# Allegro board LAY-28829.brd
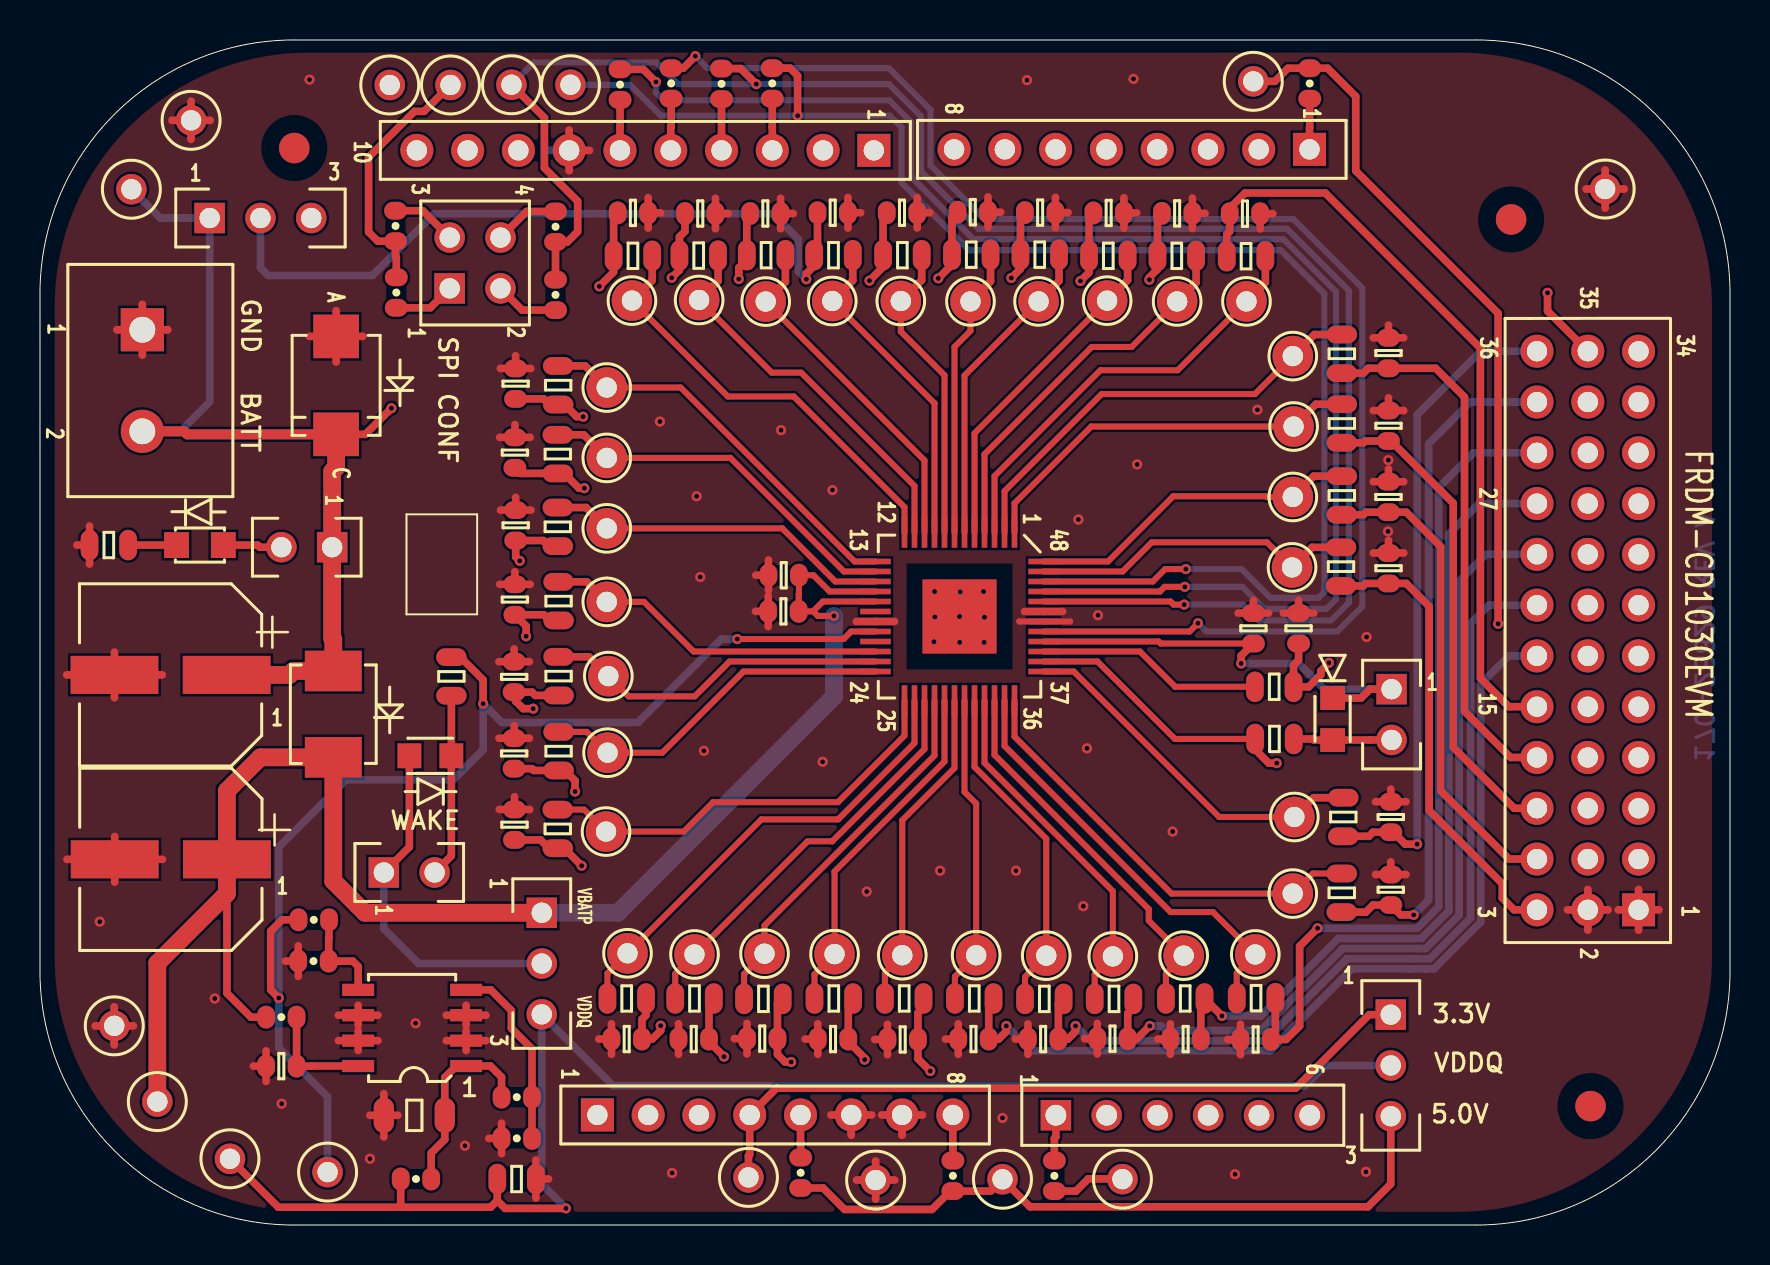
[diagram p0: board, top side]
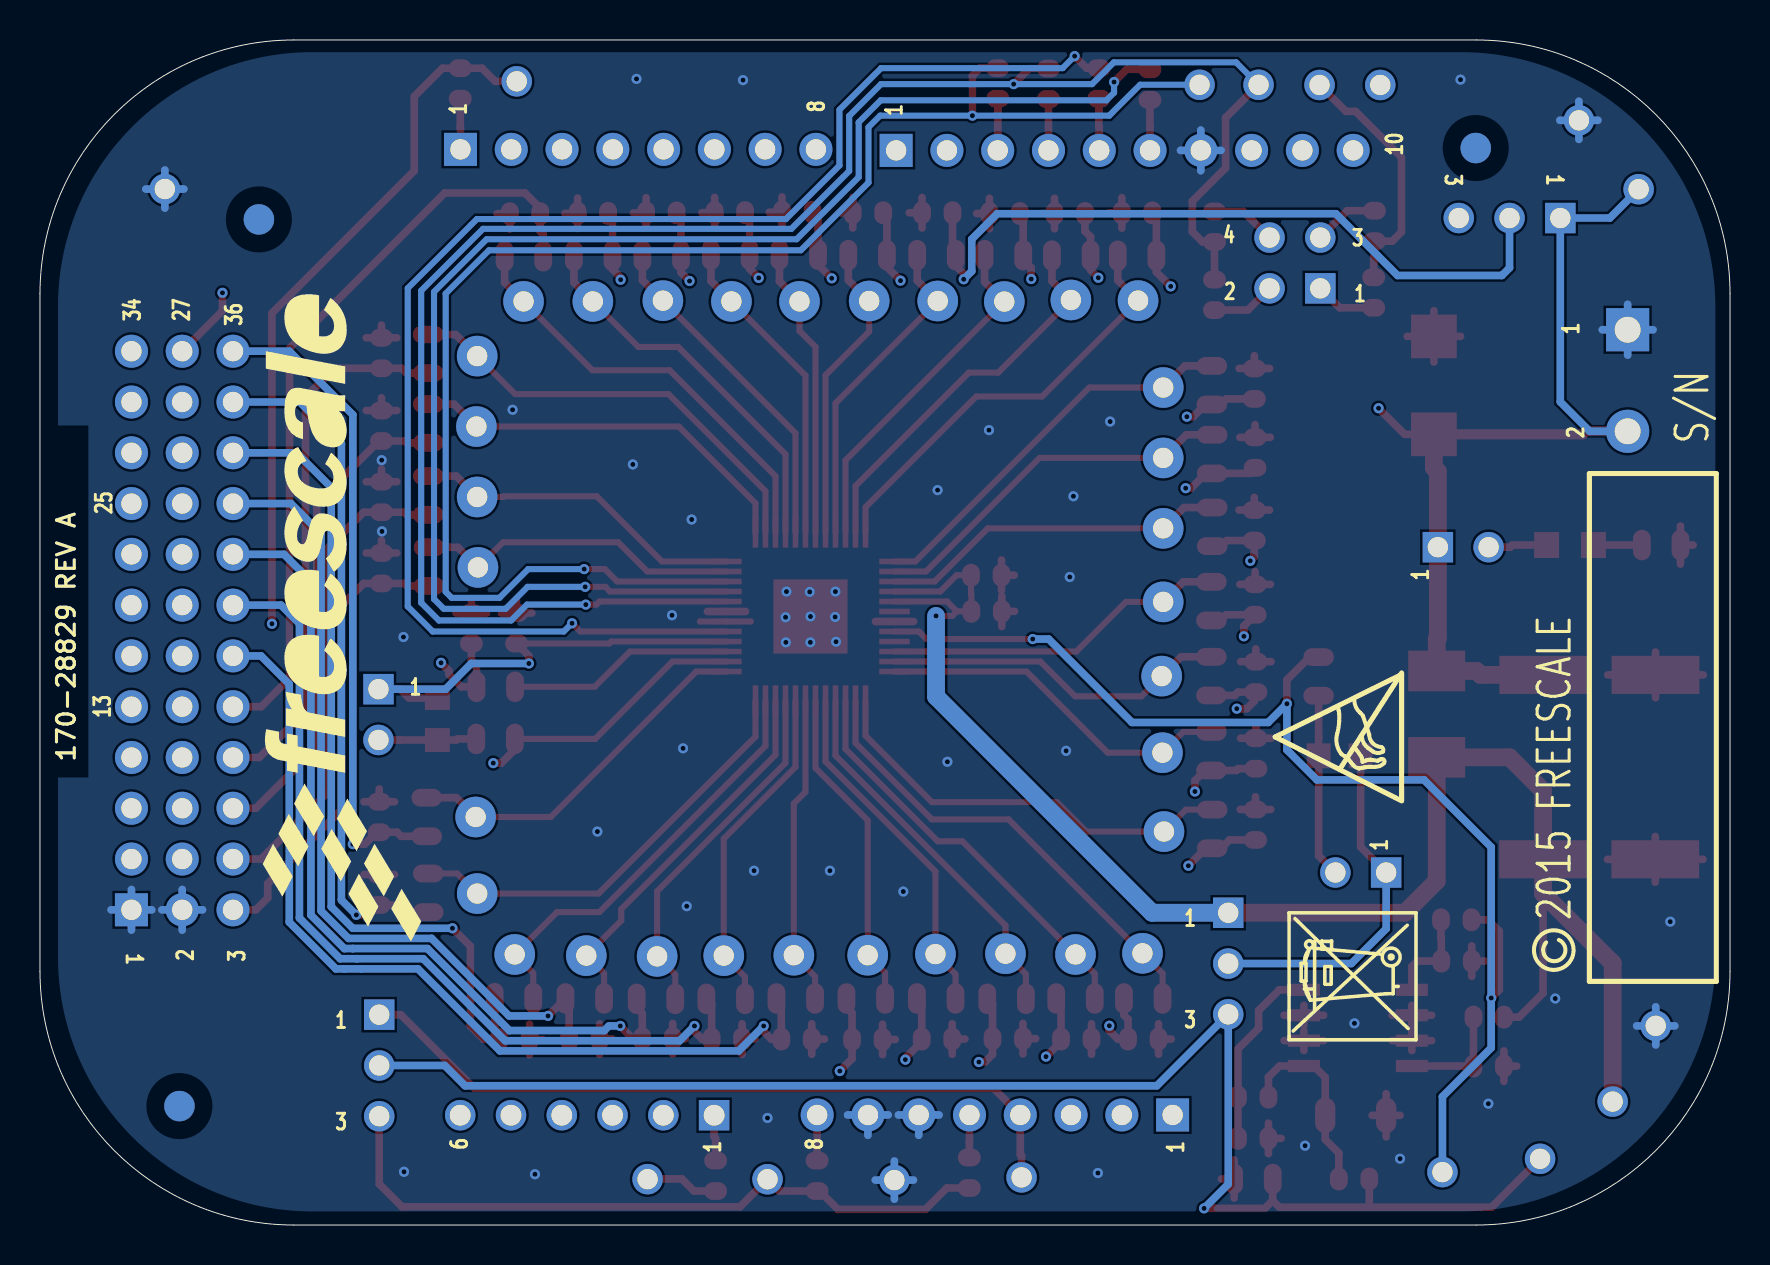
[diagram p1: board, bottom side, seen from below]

Outline 84.54 x 59.27 mm; copper layers: TOP, INNER_1, INNER_2, BOTTOM. Coordinates in mm from the lower left corner of the outline.
Outline path: 0,46.57 arc(3.72,55.55) 12.7,59.27 71.84,59.27 arc(80.82,55.55) 84.54,46.57 84.54,12.7 arc(80.82,3.72) 71.84,0 12.7,0 arc(3.72,3.72) 0,12.7 0,46.57

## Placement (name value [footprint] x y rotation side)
AMUX  TEST POINT RED  [TEST_LOOP]  54.15 2.29 0 top
BATT1  TEST POINT RED  [TEST_LOOP]  4.57 51.81 0 top
C1  0.1uF  [CC0603_OV]  56.88 50.6 0 top
C2  0.1uF  [CC0603_OV]  53.46 50.62 0 top
C3  0.1uF  [CC0603_OV]  50.03 50.64 0 top
C4  0.1uF  [CC0603_OV]  46.66 50.66 0 top
C5  0.1uF  [CC0603_OV]  43.12 50.63 0 top
C6  0.1uF  [CC0603_OV]  39.65 50.63 0 top
C7  0.1uF  [CC0603_OV]  36.28 50.59 0 top
C8  0.1uF  [CC0603_OV]  33.03 50.59 0 top
C9  0.1uF  [CC0603_OV]  29.66 50.62 0 top
C10  0.1uF  [CC0603_OV]  23.79 42.08 90 top
C11  0.1uF  [CC0603_OV]  23.76 38.64 90 top
C12  0.1uF  [CC0603_OV]  23.8 35 90 top
C13  0.1uF  [CC0603_OV]  23.76 31.29 90 top
C14  0.1uF  [CC0603_OV]  23.72 27.42 90 top
C15  0.1uF  [CC0603_OV]  23.72 23.59 90 top
C16  0.1uF  [CC0603_OV]  23.74 20.02 90 top
C17  0.1uF  [CC0603_OV]  29.35 9.3 180 top
C18  0.1uF  [CC0603_OV]  32.7 9.3 180 top
C19  0.1uF  [CC0603_OV]  36.13 9.32 180 top
C20  0.1uF  [CC0603_OV]  39.67 9.3 180 top
C21  0.1uF  [CC0603_OV]  43.15 9.28 180 top
C22  100uF  [CCE8P3X8P3]  6.55 18.29 180 top
C23  1000PF  [CC0603_OV]  62.96 29.85 90 top
C24  0.1uF  [CC0603_OV]  37.2 32.5 180 top
C25  1000PF  [CC0603_OV]  37.19 30.7 180 top
C26  0.1uF  [CC0603_OV]  60.7 29.85 90 top
C27  0.1uF  [CC0603_OV]  67.57 20.41 90 top
C28  0.1uF  [CC0603_OV]  67.57 16.77 90 top
C29  0.1uF  [CC0603_OV]  60.81 9.28 180 top
C30  0.1uF  [CC0603_OV]  57.31 9.3 180 top
C31  0.1uF  [CC0603_OV]  53.65 9.32 180 top
C32  0.1uF  [CC0603_OV]  50.18 9.3 180 top
C33  0.1uF  [CC0603_OV]  46.7 9.3 180 top
C34  0.1uF  [CC0603_OV]  60.27 50.58 0 top
C35  0.1uF  [CC0603_OV]  67.45 43.61 90 top
C36  0.1uF  [CC0603_OV]  67.45 39.98 90 top
C37  0.1uF  [CC0603_OV]  67.45 36.42 90 top
C38  0.1uF  [CC0603_OV]  67.45 32.85 90 top
C39  0.1UF  [CC0603_OV]  12.07 7.95 180 top
C40  10uF  [CC1206_OV]  18.72 5.49 180 top
C41  10uF  [CC0805_OV]  23.84 2.3 0 top
C42  100uF  [CCE8P3X8P3]  6.53 27.52 180 top
CSB  TEST POINT RED  [TEST_LOOP]  26.54 57.03 0 top
D1  ES3AB-13-F  [SMB_4P57X3P94MM]  14.67 25.55 90 top
D2  RED  [LED_2P_0805]  19.53 23.47 180 top
D3  RED  [LED_2P_0805]  64.66 25.31 90 top
D4  SMBJ40  [DO-214AA_A]  14.81 42 90 top
D5  GREEN  [LED2_2P34_2P1X1P25]  8 34.01 0 top
GND1  TEST POINT BLACK  [TEST_LOOP]  7.56 55.26 0 top
GND2  TEST POINT BLACK  [TEST_LOOP]  41.8 2.25 0 top
GND3  TEST POINT BLACK  [TEST_LOOP]  78.29 51.82 0 top
GND4  TEST POINT BLACK  [TEST_LOOP]  3.72 9.96 0 top
INTB  TEST POINT RED  [TEST_LOOP]  60.69 57.21 0 top
J1  SKT_1X10  [CON_SKT1X10_TH]  41.71 53.75 270 top
J2  SKT_1X8  [CON_SKT1X8_TH]  63.51 53.8 270 top
J3  HDR 1X2  [HDR102]  67.61 26.8 0 top
J4  HDR 1X2  [HDR102]  14.62 33.9 270 top
J5  OSTTC022162  [CON2_TB_5P08_TH_OSTTC]  5.12 44.78 270 top
J6  HDR_1X3  [HDR103]  25.1 15.62 0 top
J7  HDR 1X2  [HDR102]  17.2 17.63 90 top
J8  SKT_1X8  [CON_SKT1X8_TH]  27.88 5.5 90 top
J9  SKT_1X6  [CON_SKT1X6_TH]  50.82 5.49 90 top
J14  HDR_1X3  [HDR103]  67.57 10.52 0 top
J15  HDR_1X3  [HDR103]  8.49 50.37 90 top
J16  HDR_3X12  [HDR_3X12_100_TH]  79.96 15.77 90 top
J17  SKT_2X2  [SKT2X2_TH_SSQ]  20.5 46.85 180 top
MISO  TEST POINT RED  [TEST_LOOP]  20.53 57.02 0 top
MOSI  TEST POINT RED  [TEST_LOOP]  23.58 57.03 0 top
NOREF  -  [unnamed]  77.56 5.95 0 top
NOREF#2  -  [#2]  5.87 6.17 0 top
NOREF#3  -  [#2]  48.75 26.23 90 top
NOREF#4  -  [#2]  0 46.57 0 top
NOREF#5  -  [#2]  71.84 0 90 top
NOREF#6  -  [#2]  -381.99 188.19 0 top
NOREF#7  -  [#2]  41.79 27.68 0 top
NOREF#8  -  [#2]  50.2 27.68 90 top
NOREF#9  -  [#2]  5.04 56.7 0 top
NOREF#10  -  [unnamed]  12.72 53.87 0 top
NOREF#11  -  [#2]  -16.61 -33.78 0 top
NOREF#12  -  [#2]  48.79 33.61 90 top
NOREF#13  -  [#2]  46 30.44 90 top
NOREF#14  -  [#2]  -408.02 -336.95 0 top
NOREF#15  -  [#2]  10.52 29.44 0 top
NOREF#16  -  [#2]  5.87 6.17 0 top
NOREF#17  -  [unnamed]  73.59 50.3 0 top
NOREF#18  -  [#2]  5.87 6.17 0 top
NOREF#19  -  [#2]  41.79 30.19 0 top
NOREF#20  -  [#2]  230.3 -47.15 0 top
NOREF#21  -  [#2]  42.06 40.34 0 top
NOREF#22  -  [#2]  43.24 34.64 0 top
NOREF#23  -  [#2]  29.39 39.36 90 top
NOREF#24  -  [#2]  20.5 46.85 90 top
NOREF#25  -  [#2]  230.3 -73.82 90 top
NOREF#26  -  [#2]  41.79 27.68 90 top
NOREF#27  -  [#2]  13.04 10.1 270 bottom
NOREF#28  -  [#2]  54.59 8.44 180 bottom
NOREF#29  -  [#2]  72.49 18.67 90 bottom
NOREF#30  -  [unnamed]  77.56 5.95 180 bottom
NOREF#31  -  [#2]  7.64 8.5 180 bottom
NOREF#32  -  [#2]  10.52 29.44 0 bottom
NOREF#33  -  [unnamed]  73.59 50.3 180 bottom
NOREF#34  -  [#2]  26.4 23.29 90 bottom
NOREF#35  -  [#2]  91.8 42.45 180 bottom
NOREF#36  -  [#2]  54.64 15.8 180 bottom
NOREF#37  -  [#2]  22.27 8.86 90 bottom
NOREF#38  -  [unnamed]  12.72 53.87 180 bottom
R1  100  [RC0805_OV]  56.87 48.48 0 top
R2  100  [RC0805_OV]  53.44 48.48 0 top
R3  100  [RC0805_OV]  50.01 48.53 0 top
R4  100  [RC0805_OV]  46.58 48.53 0 top
R5  100  [RC0805_OV]  43.14 48.51 0 top
R6  100  [RC0805_OV]  39.69 48.51 0 top
R7  100  [RC0805_OV]  36.32 48.51 0 top
R8  100  [RC0805_OV]  32.95 48.49 0 top
R9  100  [RC0805_OV]  29.66 48.48 0 top
R10  100  [RC0805_OV]  25.92 42.01 90 top
R11  100  [RC0805_OV]  25.9 38.56 90 top
R12  100  [RC0805_OV]  25.9 34.92 90 top
R13  100  [RC0805_OV]  25.94 31.21 90 top
R14  100  [RC0805_OV]  25.94 27.45 90 top
R15  100  [RC0805_OV]  25.94 23.7 90 top
R16  100  [RC0805_OV]  25.9 19.81 90 top
R17  100  [RC0805_OV]  29.35 11.33 180 top
R18  100  [RC0805_OV]  32.74 11.33 180 top
R19  100  [RC0805_OV]  36.19 11.31 180 top
R20  100  [RC0805_OV]  39.71 11.33 180 top
R21  100  [RC0805_OV]  43.23 11.33 180 top
R22  1K  [RC0805_OV]  61.74 26.92 180 top
R23  10K  [RC0805_OV]  61.75 24.31 0 top
R24  100  [RC0805_OV]  65.08 32.93 270 top
R25  100  [RC0805_OV]  65.12 36.49 270 top
R26  100  [RC0805_OV]  65.12 40.09 270 top
R27  100  [RC0805_OV]  65.12 43.58 270 top
R28  100  [RC0805_OV]  60.33 48.46 180 top
R29  100  [RC0805_OV]  46.73 11.33 0 top
R30  100  [RC0805_OV]  50.24 11.31 0 top
R31  100  [RC0805_OV]  53.73 11.31 0 top
R32  100  [RC0805_OV]  57.29 11.33 0 top
R33  100  [RC0805_OV]  60.83 11.35 0 top
R34  100  [RC0805_OV]  65.12 16.62 270 top
R35  100  [RC0805_OV]  65.19 20.41 270 top
R36  10K  [RC0805_OV]  20.58 27.44 270 top
R37  0  [RC0603_OV]  36.63 57.1 270 top
R38  0  [RC0603_OV]  29.02 57.04 270 top
R39  0  [RC0603_OV]  31.57 57.1 270 top
R40  0  [RC0603_OV]  34.09 57.08 270 top
R41  0  [RC0603_OV]  63.52 57.1 270 top
R42  0  [RC0603_OV]  18.81 2.3 180 top
R43  0  [RC0603_OV]  12.07 10.4 0 top
R44  10K  [RC0805_OV]  3.44 34.01 0 top
R45  0  [RC0603_OV]  38.05 2.61 90 top
R46  0  [RC0603_OV]  45.67 2.46 90 top
R47  0  [RC0603_OV]  50.74 2.46 90 top
R48  0  [RC0603_OV]  17.82 46.64 90 top
R49  0  [RC0603_OV]  17.79 49.97 270 top
R50  0  [RC0603_OV]  25.79 46.53 270 top
R51  0  [RC0603_OV]  25.79 49.93 90 top
R61  47K  [RC0603_OV]  23.85 6.4 180 top
R62  150.0K  [RC0603_OV]  23.85 4.33 180 top
R63  0  [RC0603_OV]  13.68 13.2 0 top
R64  0  [RC0603_OV]  13.7 15.27 0 top
SCLK  TEST POINT RED  [TEST_LOOP]  17.5 57.02 0 top
SG0  TH  [MST_TESTPOINT]  56.88 46.2 0 top
SG1  TH  [MST_TESTPOINT]  53.38 46.24 0 top
SG2  TH  [MST_TESTPOINT]  49.95 46.2 0 top
SG3  TH  [MST_TESTPOINT]  46.55 46.2 0 top
SG4  TH  [MST_TESTPOINT]  43.06 46.22 0 top
SG5  TH  [MST_TESTPOINT]  39.63 46.22 0 top
SG6  TH  [MST_TESTPOINT]  36.3 46.19 0 top
SG7  TH  [MST_TESTPOINT]  32.97 46.27 0 top
SG8  TH  [MST_TESTPOINT]  29.61 46.24 0 top
SG9  TH  [MST_TESTPOINT]  28.35 41.89 0 top
SG10  TH  [MST_TESTPOINT]  28.35 38.37 0 top
SG11  TH  [MST_TESTPOINT]  28.35 34.85 0 top
SG12  TH  [MST_TESTPOINT]  28.35 31.17 0 top
SG13  TH  [MST_TESTPOINT]  28.43 27.45 0 top
SG14  TH  [MST_TESTPOINT]  28.39 23.62 0 top
SG15  TH  [MST_TESTPOINT]  28.32 19.68 0 top
SG16  TH  [MST_TESTPOINT]  29.39 13.59 0 top
SG17  TH  [MST_TESTPOINT]  32.74 13.53 0 top
SG18  TH  [MST_TESTPOINT]  36.24 13.57 0 top
SG19  TH  [MST_TESTPOINT]  39.75 13.55 0 top
SG20  TH  [MST_TESTPOINT]  43.13 13.5 0 top
SP0  TH  [MST_TESTPOINT]  62.63 32.89 0 top
SP1  TH  [MST_TESTPOINT]  62.67 36.42 0 top
SP2  TH  [MST_TESTPOINT]  62.71 39.94 0 top
SP3  TH  [MST_TESTPOINT]  62.67 43.46 0 top
SP4  TH  [MST_TESTPOINT]  60.35 46.2 0 top
SP5  TH  [MST_TESTPOINT]  46.83 13.5 0 top
SP6  TH  [MST_TESTPOINT]  50.34 13.47 0 top
SP7  TH  [MST_TESTPOINT]  53.67 13.44 0 top
SP8  TH  [MST_TESTPOINT]  57.21 13.47 0 top
SP9  TH  [MST_TESTPOINT]  60.79 13.53 0 top
SP10  TH  [MST_TESTPOINT]  62.67 16.58 0 top
SP11  TH  [MST_TESTPOINT]  62.75 20.41 0 top
U1  PC33CD1030  [LQFP48_EP146MIL]  46 30.44 270 top
U2  LM2931CDG  [SO8_1P27_4X5]  18.62 9.86 180 top
UNK3V3  TEST POINT RED  [TEST_LOOP]  35.44 2.38 0 top
UNK5V0  TEST POINT RED  [TEST_LOOP]  48.15 2.29 0 top
VBATP  TEST POINT RED  [TEST_LOOP]  5.87 6.17 0 top
VDDQ  TEST POINT RED  [TEST_LOOP]  9.5 3.31 0 top
WAKE_B  TEST POINT RED  [TEST_LOOP]  14.39 2.65 0 top

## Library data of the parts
AMUX BATT1 CSB GND1-GND4 INTB MISO MOSI SCLK UNK3V3 UNK5V0 VBATP VDDQ WAKE_B = TestLoop
C1-C21 C23-C41 = CAP_NP
C22 C42 = CAP_POL
D1 = DIODE
D2 D3 D5 = LED
D4 = DIODE_TVS
J1 = CONN_HDR_10X1
J2 J8 = CONN_HDR_8X1
J3-J5 J7 = CONN_HDR_2X1
J6 J14 J15 = CONN_HDR_3X1
J9 = CONN_HDR_6X1
J16 = HDR-3X12
J17 = CONN_HDR_2X2
R1-R51 R61-R64 = RES
SG0-SG20 SP0-SP11 = T POINT S
U1 = CD1030_LQFP48_EP
U2 = LM2931_SO8

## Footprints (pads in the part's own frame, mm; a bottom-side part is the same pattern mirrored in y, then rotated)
CC0603_OV
  oval 0.889x1.143 smd: 1(-0.762,0) 2(0.762,0)
CC0805_OV
  oval 0.889x1.524 smd: 1(-0.965,0) 2(0.965,0)
CC1206_OV
  oval 1.016x1.778 smd: 1(-1.524,0) 2(1.524,0)
CCE8P3X8P3
  rect 4.394x1.905 smd: 1(-2.807,0) 2(2.807,0)
CON2_TB_5P08_TH_OSTTC
  rect 2.159x2.159 hole 1.295: 1(0,0)
  round 2.159 hole 1.295: 2(5.08,0)
CON_SKT1X6_TH
  rect 1.524x1.524 hole 1.041: 1(0,0)
  round 1.524 hole 1.041: 2(0,-2.54) 3(0,-5.08) 4(0,-7.62) 5(0,-10.16) 6(0,-12.7)
CON_SKT1X8_TH
  rect 1.651x1.651 hole 1.016: 1(0,0)
  round 1.651 hole 1.016: 2(0,-2.54) 3(0,-5.08) 4(0,-7.62) 5(0,-10.16) 6(0,-12.7) 7(0,-15.24) 8(0,-17.78)
CON_SKT1X10_TH
  rect 1.651x1.651 hole 1.016: 1(0,0)
  round 1.651 hole 1.016: 2(0,-2.54) 3(0,-5.08) 4(0,-7.62) 5(0,-10.16) 6(0,-12.7) 7(0,-15.24) 8(0,-17.78) 9(0,-20.32) 10(0,-22.86)
DO-214AA_A
  rect 2.184x2.286 smd: A(2.45,0) C(-2.45,0)
HDR102
  rect 1.524x1.524 hole 1.016: 1(0,0)
  round 1.524 hole 1.016: 2(0,-2.54)
HDR103
  rect 1.524x1.524 hole 1.016: 1(0,0)
  round 1.524 hole 1.016: 2(0,-2.54) 3(0,-5.08)
HDR_3X12_100_TH
  rect 1.651x1.651 hole 1.016: 1(0,0)
  round 1.651 hole 1.016: 2(0,2.54) 3(0,5.08) 4(2.54,0) 5(2.54,2.54) 6(2.54,5.08) 7(5.08,0) 8(5.08,2.54) 9(5.08,5.08) 10(7.62,0) 11(7.62,2.54) 12(7.62,5.08) 13(10.16,0) 14(10.16,2.54) 15(10.16,5.08) 16(12.7,0) 17(12.7,2.54) 18(12.7,5.08) 19(15.24,0) 20(15.24,2.54) 21(15.24,5.08) 22(17.78,0) 23(17.78,2.54) 24(17.78,5.08) 25(20.32,0) 26(20.32,2.54) 27(20.32,5.08) 28(22.86,0) 29(22.86,2.54) 30(22.86,5.08) 31(25.4,0) 32(25.4,2.54) 33(25.4,5.08) 34(27.94,0) 35(27.94,2.54) 36(27.94,5.08)
LED2_2P34_2P1X1P25
  rect 1.245x1.295 smd: A(1.172,0) C(-1.172,0)
LED_2P_0805
  rect 1.194x1.245 smd: A(1.05,0) C(-1.05,0)
LQFP48_EP146MIL
  rect 1.524x0.279 smd: 1(-4.204,2.752) 2(-4.204,2.252) 3(-4.204,1.751) 4(-4.204,1.251) 5(-4.204,0.751) 6(-4.204,0.25) 7(-4.204,-0.25) 8(-4.204,-0.751) 9(-4.204,-1.251) 10(-4.204,-1.751) 11(-4.204,-2.252) 12(-4.204,-2.752) 25(4.204,-2.752) 26(4.204,-2.252) 27(4.204,-1.751) 28(4.204,-1.251) 29(4.204,-0.751) 30(4.204,-0.25) 31(4.204,0.25) 32(4.204,0.751) 33(4.204,1.251) 34(4.204,1.751) 35(4.204,2.252) 36(4.204,2.752)
  rect 0.279x1.524 smd: 13(-2.752,-4.204) 14(-2.252,-4.204) 15(-1.751,-4.204) 16(-1.251,-4.204) 17(-0.751,-4.204) 18(-0.25,-4.204) 19(0.25,-4.204) 20(0.751,-4.204) 21(1.251,-4.204) 22(1.751,-4.204) 23(2.252,-4.204) 24(2.752,-4.204) 37(2.752,4.204) 38(2.252,4.204) 39(1.751,4.204) 40(1.251,4.204) 41(0.751,4.204) 42(0.25,4.204) 43(-0.25,4.204) 44(-0.751,4.204) 45(-1.251,4.204) 46(-1.751,4.204) 47(-2.252,4.204) 48(-2.752,4.204)
  rect 3.708x3.708 smd: 49(0,0)
MST_TESTPOINT
  round 2.032 hole 1.016: 1(0,0)
RC0603_OV
  oval 0.889x1.143 smd: 1(-0.762,0) 2(0.762,0)
RC0805_OV
  oval 0.889x1.524 smd: 1(-0.965,0) 2(0.965,0)
SKT2X2_TH_SSQ
  rect 1.524x1.524 hole 1.016: 1(0,0)
  round 1.524 hole 1.016: 2(-2.54,0) 3(0,-2.54) 4(-2.54,-2.54)
SMB_4P57X3P94MM
  rect 2.032x2.845 smd: A(2.16,0) C(-2.16,0)
SO8_1P27_4X5
  rect 1.6x0.61 smd: 1(-2.7,1.905) 2(-2.7,0.635) 3(-2.7,-0.635) 4(-2.7,-1.905) 5(2.7,-1.905) 6(2.7,-0.635) 7(2.7,0.635) 8(2.7,1.905)
TEST_LOOP
  round 1.524 hole 1.016: 1(0,0)
unnamed
  round 1.524 smd: (0,0)

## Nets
3V3_MCU: J8.4 J14.1 UNK3V3.1
5V0_MCU: J14.3 R45.1 R46.1 UNK5V0.1
VBATP: C22.1 C24.1 C25.1 D1.C(CATHODE) J6.1 R43.1 U1.16(VBATP1) U1.17(VBATP2) VBATP.1(PIN1)
VDDQ: C26.1 C41.1 D3.A(ANODE) J3.1 J6.3 J14.2 R42.2 U1.40(VDDQ) VDDQ.1(PIN1)
0: C1.2 C2.2 C3.2 C4.2 C5.2 C6.2 C7.2 C8.2 C9.2 C10.2 C11.2 C12.2 C13.2 C14.2 C15.2 C16.2 C17.2 C18.2 C19.2 C20.2 C21.2 C22.2 C23.2 C24.2 C25.2 C26.2 C27.2 C28.2 C29.2 C30.2 C31.2 C32.2 C33.2 C34.2 C35.2 C36.2 C37.2 C38.2 C39.2 C40.2 C41.2 C42.2 D4.A GND1.1(PIN1) GND2.1(PIN1) GND3.1(PIN1) GND4.1(PIN1) J1.7 J5.1 J8.6 J8.7 J16.1 J16.2 R44.1 R62.2 R63.1 U1.19(GND1) U1.42(GND2) U1.43(GND3) U1.49(EP_GND) U2.2(GND1) U2.3(GND2) U2.6(GND3) U2.7(GND4)
AMUX: AMUX.1(PIN1) C23.1 R22.1 R47.1
BATTERY: BATT1.1(PIN1) C42.1 D1.A(ANODE) D4.C J4.1 J5.2 J15.1 J16.35
CS_B: CSB.1(PIN1) R37.1 U1.46(C\S\)
CSB_M: J1.3 R37.2
INT_B: INTB.1(PIN1) R23.1 R41.1 U1.38(I\N\T\)
INTB_M: J2.1 R41.2
MISO: MISO.1(PIN1) R39.1 R48.2 R49.2 U1.41(MISO)
MISO_M: J1.5 R39.2
MOSI: MOSI.1(PIN1) R40.1 R50.1 R51.1 U1.44(MOSI)
MOSI_M: J1.4 R40.2
OUT: C40.1 R42.1 R61.2 U2.1(OUT)
SCLK: R38.1 SCLK.1(PIN1) U1.45(SCLK)
SCLK_M: J1.6 R38.2
SG0: R1.2 SG0.1(TP) U1.4(SG0)
SG0R: C1.1 J16.4 R1.1
SG1: R2.2 SG1.1(TP) U1.5(SG1)
SG1R: C2.1 J16.7 R2.1
SG2: R3.2 SG2.1(TP) U1.6(SG2)
SG2R: C3.1 J16.10 R3.1
SG3: R4.2 SG3.1(TP) U1.7(SG3)
SG3R: C4.1 J16.13 R4.1
SG4: R5.2 SG4.1(TP) U1.8(SG4)
SG4R: C5.1 J16.16 R5.1
SG5: R6.2 SG5.1(TP) U1.9(SG5)
SG5R: C6.1 J15.2 R6.1
SG5RX: J15.3 J16.19
SG6: R7.2 SG6.1(TP) U1.10(SG6)
SG6R: C7.1 J16.22 R7.1
SG7: R8.2 SG7.1(TP) U1.11(SG7)
SG7R: C8.1 J16.25 R8.1
SG8: R9.2 SG8.1(TP) U1.12(SG8)
SG8R: C9.1 J16.28 R9.1
SG9: R10.2 SG9.1(TP) U1.13(SG9)
SG9R: C10.1 J16.31 R10.1
SG10: R11.2 SG10.1(TP) U1.14(SG10)
SG10R: C11.1 J16.34 R11.1
SG11: R12.2 SG11.1(TP) U1.15(SG11)
SG11R: C12.1 J16.32 R12.1
SG12: R13.2 SG12.1(TP) U1.22(SG12)
SG12R: C13.1 J16.29 R13.1
SG13: R14.2 SG13.1(TP) U1.23(SG13)
SG13R: C14.1 J16.26 R14.1
SG14: R15.2 SG14.1(TP) U1.24(SG14)
SG14R: C15.1 J16.23 R15.1
SG15: R16.2 SG15.1(TP) U1.25(SG15)
SG15R: C16.1 J16.20 R16.1
SG16: R17.2 SG16.1(TP) U1.26(SG16)
SG16R: C17.1 J16.17 R17.1
SG17: R18.2 SG17.1(TP) U1.27(SG17)
SG17R: C18.1 J16.14 R18.1
SG18: R19.2 SG18.1(TP) U1.28(SG18)
SG18R: C19.1 J16.11 R19.1
SG19: R20.2 SG19.1(TP) U1.29(SG19)
SG19R: C20.1 J16.8 R20.1
SG20: R21.2 SG20.1(TP) U1.30(SG20)
SG20R: C21.1 J16.5 R21.1
SP0: R24.1 SP0.1(TP) U1.47(SP0)
SP0R: C38.1 J16.3 R24.2
SP1: R25.1 SP1.1(TP) U1.48(SP1)
SP1R: C37.1 J16.6 R25.2
SP2: R26.1 SP2.1(TP) U1.1(SP2)
SP2R: C36.1 J16.9 R26.2
SP3: R27.1 SP3.1(TP) U1.2(SP3)
SP3R: C35.1 J16.12 R27.2
SP4: R28.1 SP4.1(TP) U1.3(SP4)
SP4R: C34.1 J16.15 R28.2
SP5: R29.1 SP5.1(TP) U1.31(SP5)
SP5R: C33.1 J16.18 R29.2
SP6: R30.1 SP6.1(TP) U1.32(SP6)
SP6R: C32.1 J16.21 R30.2
SP7: R31.1 SP7.1(TP) U1.33(SP7)
SP7R: C31.1 J16.24 R31.2
SP8: R32.1 SP8.1(TP) U1.34(SP8)
SP8R: C30.1 J16.27 R32.2
SP9: R33.1 SP9.1(TP) U1.35(SP9)
SP9R: C29.1 J16.30 R33.2
SP10: R34.1 SP10.1(TP) U1.36(SP10)
SP10R: C28.1 J16.33 R34.2
SP11: R35.1 SP11.1(TP) U1.37(SP11)
SP11R: C27.1 J16.36 R35.2
WAKE_B: R36.1 R64.1 U1.20(W\A\K\E\) WAKE_B.1(PIN1)
N46347: R22.2 U1.39(AMUX)
N63980: D2.A(ANODE) J6.2 J7.1
N64526: D2.C(CATHODE) J7.2 R36.2
N74267: D3.C(CATHODE) J3.2 R23.2
N81888: D5.A(ANODE) J4.2
N159644: J8.5 R45.2
N159652: J8.8 R46.2
N165115: J9.1 R47.2
N222829: C39.1 R43.2 U2.8(IN)
N224295: R61.1 R62.1 U2.4(ADJ)
N235544: R63.2 R64.2 U2.5(OUT_INH)
N794881: D5.C(CATHODE) R44.2
N1652480: J17.1(A1) R48.1
N1652481: J17.2(B1) R50.2
N1652482: J17.3(A2) R49.1
N1652483: J17.4(B2) R51.2

Pads without a net: J1 1 2 8 9 10; J2 2 3 4 5 6 7 8; J8 1 2 3; J9 2 3 4 5 6; U1 18 21

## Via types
v1: diameter 0.508, hole 0.254, TOP to BOTTOM, 89 vias

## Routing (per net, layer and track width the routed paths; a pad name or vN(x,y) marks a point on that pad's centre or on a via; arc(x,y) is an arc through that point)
3V3_MCU: length 37.3
  TOP w0.381: J14.1 66.49,10.52 62.81,6.85 36.84,6.85 J8.4 35.5,3.53 35.44,3.46 UNK3V3.1
5V0_MCU: length 35
  TOP w0.381: R45.1 39.17,1.85 40.25,0.78 44.62,0.78 45.54,1.7 R46.1 47.56,1.7 UNK5V0.1 49.52,0.91 66.43,0.91 67.57,2.05 J14.3
VBATP: length 82
  TOP w0.305: U1.17 39.17,31.19 38.67,30.7 ; 38.67,30.7 C25.1 37.95,31.55 37.97,31.56 C24.1 38.69,32.5 39.5,31.69 U1.16 ; 38.67,30.7 38.9,30.47 v1(39.72,30.47)
  TOP w0.381: 9.35,16.58 9.35,11.6 10.55,10.4 R43.1
  TOP w0.889: J6.1 16.26,15.62 14.67,17.21 D1.C 11.02,23.39 9.35,21.72 C22.1 9.35,16.58 5.87,13.1 VBATP.1
  BOTTOM w0.889: J6.1 28.91,15.62 39.72,26.43 v1(39.72,30.47)
VDDQ: length 120.2
  TOP w0.305: U1.40 55.96,29.19 56.06,29.09 C26.1
  TOP w0.381: C41.1 22.88,1.22 ; 22.88,1.22 22.55,0.89 18.04,0.89 ; 22.88,1.22 23.26,0.83 v1(26.31,0.83) ; v1(60.08,28.09) 60.08,28.47 C26.1 ; 18.04,0.89 11.92,0.89 VDDQ.1 ; 18.04,0.89 R42.2 ; J3.1 66.53,26.8 66.08,26.36 D3.A
  INNER_2 w0.381: J14.2 67.62,7.92 69.28,7.92 70.21,8.86 70.21,21.79 68.97,23.04 68.97,25.44 J3.1
  BOTTOM w0.381: v1(60.08,28.09) 62.97,28.09 64.25,26.8 J3.1 ; J14.2 64.29,7.98 63.28,6.97 28.67,6.97 J6.3 25.1,2.04 v1(26.31,0.83)
0: length 207.5
  TOP w0.305: 48.99,30.19 48.99,30.19 U1.42 51.52,30.19 51.53,30.19
  TOP w0.381: 10.68,7.95 C39.2 ; C39.2 11.31,7.19 ; C39.2 11.31,8.71 ; C25.2 36.43,31.46 ; C25.2 36.43,29.93 ; C25.2 35.79,30.7 ; J16.1 80.98,15.77 ; J16.1 78.95,15.77 ; J16.1 79.96,16.78 ; J16.1 79.96,14.75 ; U2.6 15.92,10.99 ; U2.6 14.92,10.49 ; U2.6 15.92,10 ; U2.6 16.91,10.49 ; C36.2 67.45,41.37 ; C36.2 66.69,40.74 ; C36.2 68.22,40.74 ; C14.2 23.72,28.81 ; C14.2 24.48,28.18 ; C14.2 22.96,28.18 ; 40.85,2.25 GND2.1 ; GND2.1 41.8,1.29 ; GND2.1 41.8,3.2 ; GND2.1 42.75,2.25 ; C13.2 23.76,32.68 ; C13.2 24.52,32.05 ; C13.2 22.99,32.05 ; C29.2 60.05,10.04 ; C29.2 59.41,9.28 ; C29.2 60.05,8.52 ; 77.34,51.82 GND3.1 ; GND3.1 78.29,50.87 ; GND3.1 79.25,51.82 ; GND3.1 78.29,52.77 ; 26.47,52.73 J1.7 ; J1.7 27.49,53.75 ; J1.7 26.47,54.77 ; C12.2 24.56,35.76 ; C12.2 23.03,35.76 ; C12.2 23.8,36.4 ; 41.76,9.28 C21.2 ; C21.2 42.39,10.04 ; C21.2 42.39,8.52 ; U2.3 22.31,10.49 ; U2.3 21.32,10 ; U2.3 20.32,10.49 ; U2.3 21.32,10.99 ; C23.2 62.96,31.25 ; C23.2 63.72,30.61 ; C23.2 62.19,30.61 ; 76.41,15.77 J16.2 ; J16.2 78.44,15.77 ; J16.2 77.42,16.78 ; J16.2 77.42,14.75 ; 12.92,12.44 R63.1 ; R63.1 12.92,13.96 ; R63.1 12.28,13.2 ; 5.12,43.51 J5.1 ; J5.1 3.85,44.78 ; J5.1 6.39,44.78 ; J5.1 5.12,46.05 ; 36.44,31.74 C24.2 ; C24.2 36.44,33.26 ; C24.2 35.81,32.5 ; C3.2 51.43,50.64 ; C3.2 50.79,51.4 ; C3.2 50.79,49.88 ; 13.48,44.45 D4.A ; D4.A 14.81,43.17 ; D4.A 14.81,45.73 ; D4.A 16.15,44.45 ; U2.2 21.32,9.72 ; U2.2 20.32,9.22 ; U2.2 21.32,8.73 ; U2.2 22.31,9.22 ; 23.03,42.84 C10.2 ; C10.2 23.79,43.48 ; C10.2 24.55,42.84 ; C26.2 61.46,30.61 ; C26.2 59.94,30.61 ; C26.2 60.7,31.25 ; 2.76,9.96 GND4.1 ; GND4.1 4.67,9.96 ; GND4.1 3.72,10.91 ; GND4.1 3.72,9.01 ; C33.2 45.93,10.06 ; C33.2 45.93,8.54 ; C33.2 45.3,9.3 ; C41.2 24.81,3.25 ; C41.2 24.81,1.35 ; C41.2 25.44,2.3 ; 31.94,10.06 C18.2 31.94,8.54 ; 40.58,4.49 J8.6 ; J8.6 41.6,5.5 ; J8.6 39.57,5.5 ; C6.2 40.42,51.39 ; C6.2 41.05,50.63 ; C6.2 40.42,49.87 ; 16.5,5.49 C40.2 ; C40.2 17.2,4.41 ; C40.2 17.2,6.57 ; C40.2 17.9,5.49 ; C15.2 23.72,24.98 ; C15.2 24.48,24.35 ; C15.2 22.96,24.35 ; C37.2 68.22,37.18 ; C37.2 67.45,37.81 ; C37.2 66.69,37.18 ; C28.2 68.33,17.53 ; C28.2 67.57,18.17 ; C28.2 66.81,17.53 ; 66.69,44.38 C35.2 ; C35.2 68.22,44.38 ; C35.2 67.45,45.01 ; C30.2 56.55,10.06 ; C30.2 55.91,9.3 ; C30.2 56.55,8.54 ; 34.73,9.32 C19.2 ; C19.2 35.37,8.56 ; C19.2 35.37,10.08 ; 30.42,49.86 C9.2 ; C9.2 31.06,50.62 ; C9.2 30.42,51.39 ; C1.2 57.65,51.36 ; C1.2 57.65,49.84 ; C1.2 58.28,50.6 ; 61.04,49.82 C34.2 61.67,50.58 ; 22.99,39.4 C11.2 ; C11.2 23.76,40.03 ; C11.2 24.52,39.4 ; 28.59,8.54 C17.2 ; C17.2 27.95,9.3 ; C17.2 28.59,10.06 ; 40.84,30.19 U1.19 42.75,30.19 ; 38.27,9.3 C20.2 ; C20.2 38.91,10.06 ; C20.2 38.91,8.54 ; C2.2 54.22,51.38 ; C2.2 54.85,50.62 ; C2.2 54.22,49.86 ; C7.2 37.05,51.36 ; C7.2 37.68,50.59 ; C7.2 37.05,49.83 ; 23.09,3.57 R62.2 ; R62.2 23.09,5.1 ; R62.2 22.45,4.33 ; 3.73,26.37 C42.2 ; C42.2 1.34,27.52 ; C42.2 3.73,28.66 ; C42.2 6.11,27.52 ; U2.7 16.91,9.22 ; U2.7 14.92,9.22 ; U2.7 15.92,8.73 ; U2.7 15.92,9.72 ; R44.1 2.48,34.96 ; R44.1 2.48,33.06 ; R44.1 1.84,34.01 ; GND1.1 7.56,56.21 ; GND1.1 6.61,55.26 ; GND1.1 7.56,54.3 ; GND1.1 8.51,55.26 ; C5.2 43.88,51.39 ; C5.2 44.52,50.63 ; C5.2 43.88,49.87 ; C38.2 67.45,34.25 ; C38.2 66.69,33.61 ; C38.2 68.22,33.61 ; 49.25,30.69 U1.43 51.15,30.69 ; 43.12,4.49 J8.7 ; J8.7 44.14,5.5 ; J8.7 42.11,5.5 ; 33.79,49.83 C8.2 ; C8.2 34.43,50.59 ; C8.2 33.79,51.36 ; 1.35,18.29 C22.2 ; C22.2 3.74,17.15 ; C22.2 3.74,19.43 ; C22.2 6.13,18.29 ; C31.2 52.89,10.08 ; C31.2 52.89,8.56 ; C31.2 52.25,9.32 ; 66.81,21.17 C27.2 ; C27.2 68.33,21.17 ; C27.2 67.57,21.81 ; C16.2 23.74,21.42 ; C16.2 24.5,20.78 ; C16.2 22.97,20.78 ; C4.2 47.42,51.42 ; C4.2 47.42,49.9 ; C4.2 48.06,50.66 ; 49.42,8.54 C32.2 ; C32.2 49.42,10.06 ; C32.2 48.78,9.3
  BOTTOM w0.381: 77.34,51.82 GND3.1 ; GND3.1 78.29,52.77 ; GND3.1 79.25,51.82 ; GND3.1 78.29,50.87 ; 39.57,5.5 J8.6 ; J8.6 41.6,5.5 ; J8.6 40.58,4.49 ; 2.76,9.96 GND4.1 ; GND4.1 3.72,10.91 ; GND4.1 4.67,9.96 ; GND4.1 3.72,9.01 ; 77.42,14.75 J16.2 ; J16.2 78.44,15.77 ; J16.2 76.41,15.77 ; J16.2 77.42,16.78 ; GND2.1 42.75,2.25 ; GND2.1 40.85,2.25 ; GND2.1 41.8,3.2 ; GND2.1 41.8,1.29 ; 25.46,53.75 J1.7 ; J1.7 26.47,54.77 ; J1.7 26.47,52.73 ; J1.7 27.49,53.75 ; 78.95,15.77 J16.1 ; J16.1 79.96,14.75 ; J16.1 79.96,16.78 ; J16.1 80.98,15.77 ; J5.1 6.39,44.78 ; J5.1 3.85,44.78 ; J5.1 5.12,46.05 ; J5.1 5.12,43.51 ; GND1.1 7.56,56.21 ; GND1.1 8.51,55.26 ; GND1.1 7.56,54.3 ; GND1.1 6.61,55.26 ; 42.11,5.5 J8.7 ; J8.7 44.14,5.5 ; J8.7 43.12,4.49
  vias: v1(2.99,15.17) v1(8.74,11.33) v1(12.09,6.07) v1(13.48,57.29) v1(16.5,3.32) v1(18.79,10.09) v1(21.26,3.97) v1(31.01,40.19) v1(31.62,2.6) v1(32.84,36.45) v1(33.03,32.41) v1(33.21,23.72) v1(37.07,39.76) v1(39.15,23.17) v1(39.64,36.76) v1(41.35,16.68) v1(44.72,29.17) v1(44.75,31.68) v1(44.76,30.41) v1(45.03,17.72) v1(46,30.44) v1(46,29.14) v1(46.03,31.67) v1(47.2,31.68) v1(47.24,30.4) v1(47.23,29.14) v1(48.15,5.35) v1(48.82,17.72) v1(49.37,57.27) v1(51.94,35.29) v1(52.19,15.95) v1(52.37,23.84) v1(52.92,30.5) v1(54.7,57.33) v1(54.88,38.04) v1(56.66,19.68) v1(59.78,2.54) v1(60.9,40.78) v1(66.36,29.41) v1(66.33,2.66) v1(67.45,38.26) v1(67.43,34.69)
AMUX: length 42.2
  TOP w0.381: AMUX.1 54.13,2.31 52.43,2.31 51.82,1.7 R47.1 ; C23.1 62.96,28.25 62.7,28 R22.1 63.47,26.92 64.07,27.53 64.07,27.72 v1(64.48,28.12)
  INNER_2 w0.381: AMUX.1 54.15,3.37 54.65,3.87 54.65,6.22 55.53,7.1 62.05,7.1 64.48,9.53 v1(64.48,28.12)
BATTERY: length 119.9
  TOP w0.381: D4.C 16.27,39.55 v1(17.58,40.85) ; J16.35 75.41,45.72 v1(75.41,46.63)
  TOP w0.508: J5.2 7.21,39.7 7.36,39.55 D4.C
  TOP w0.889: D4.C 14.81,37.89 14.62,37.69 J4.1 14.62,29.36 14.67,29.3 D1.A 12.68,27.71 12.48,27.52 C42.1
  INNER_1 w0.381: v1(75.41,46.63) 68.53,46.63 64.56,50.59 19.55,50.59 17.58,48.62 v1(17.58,40.85)
  BOTTOM w0.381: BATT1.1 6.01,50.37 J15.1 8.49,41.17 7.02,39.7 J5.2
CS_B: length 77
  TOP w0.305: U1.46 55.66,32.19 56.28,32.81 56.78,32.81 56.79,32.81 v1(57.32,32.81)
  TOP w0.381: R37.1 37.52,57.86 37.9,57.49 v1(37.9,55.49)
  BOTTOM w0.305: CSB.1 29.51,57.03 31.05,55.49 v1(37.9,55.49) 42.51,55.49 43.1,54.91 43.1,52.14 46.48,48.76 62.08,48.76 64.25,46.58 64.25,31.67 63.94,31.37 61.55,31.37 60.12,32.81 v1(57.32,32.81)
CSB_M: length 2.6
  TOP w0.381: J1.3 36.63,54.91 36.63,54.91 R37.2
INT_B: length 65.6
  TOP w0.305: R23.1 56.77,24.31 52.9,28.19 U1.38
  TOP w0.381: v1(61.86,23.1) 61.46,23.1 60.78,23.78 R23.1 ; v1(72.94,30.07) 72.94,45.61 65.82,52.73 65.82,56.45 64.4,57.86 R41.1 62.43,57.86 61.77,57.21 INTB.1
  INNER_1 w0.381: v1(72.94,30.07) 69.7,26.83 69.7,23.6 68.8,22.7 62.27,22.7 v1(61.86,23.1)
INTB_M: length 2.5
  TOP w0.381: R41.2 63.52,54.89 63.51,54.88 J2.1
MISO: length 101.3
  TOP w0.305: v1(57.92,30.1) 57.51,29.69 U1.41
  TOP w0.381: R48.2 17.82,48.41 17.79,48.45 R49.2 16.9,49.21 16.44,49.67 16.44,53.41 18.73,55.7 19.21,55.7 MISO.1 ; R39.1 32.18,57.86 v1(32.78,58.47)
  INNER_1 w0.381: MISO.1 22.23,55.33 30.23,55.33 32.78,57.88 v1(32.78,58.47)
  BOTTOM w0.305: v1(32.78,58.47) 33.39,57.86 42.47,57.86 44.55,55.78 44.55,52.99 47.23,50.32 62.68,50.32 66.14,46.86 66.14,30.94 64.89,29.69 58.34,29.69 v1(57.92,30.1)
MISO_M: length 2.6
  TOP w0.381: J1.5 31.55,54.91 31.57,54.93 R39.2
MOSI: length 94.3
  TOP w0.305: U1.44 56.55,31.19 56.7,31.03 v1(57.24,31.03)
  TOP w0.381: MOSI.1 25.23,55.38 25.23,52.87 26.9,51.21 26.9,49.68 26.38,49.17 R51.1 R50.1 ; R40.1 35.06,57.84 v1(35.83,57.06)
  BOTTOM w0.305: MOSI.1 24.7,58.15 30.82,58.15 31.91,57.06 v1(35.83,57.06) 42.47,57.06 44.06,55.47 44.06,52.72 46.95,49.83 62.38,49.83 65.47,46.73 65.47,31.13 64.58,30.24 60.97,30.24 60.18,31.03 v1(57.24,31.03)
MOSI_M: length 2.6
  TOP w0.381: R40.2 J1.4
OUT: length 9.7
  TOP w0.381: R42.1 19.57,3.6 20.25,4.28 C40.1 20.25,7.38 20.82,7.95 U2.1 22.53,7.95 23.09,7.4 R61.2
SCLK: length 87.3
  TOP w0.305: v1(57.27,31.92) 56.26,31.92 56.02,31.69 U1.45
  TOP w0.381: v1(30.81,57.17) 30.18,57.81 R38.1
  INNER_1 w0.381: SCLK.1 18.61,58.14 29.84,58.14 v1(30.81,57.17)
  BOTTOM w0.305: v1(30.81,57.17) 30.81,56.64 31.19,56.26 42.48,56.26 43.59,55.15 43.59,52.41 46.69,49.31 62.2,49.31 64.83,46.68 64.83,31.31 64.34,30.82 61.25,30.82 60.15,31.92 v1(57.27,31.92)
SCLK_M: length 2.5
  TOP w0.381: J1.6 29.01,54.91 29.02,54.91 R38.2
SG0: length 19.4
  TOP w0.305: SG0.1 54.6,43.92 52.61,43.92 47.25,38.55 U1.4
  TOP w0.381: R1.2 57.83,47.14 SG0.1
SG0R: length 49.2
  TOP w0.381: C1.1 55.9,50.38 R1.1 55.9,47.81 55.49,47.4 v1(55.49,47.28)
  INNER_2 w0.381: J16.4 78.74,19.53 73.77,19.53 69.62,23.69 69.62,38.88 60.98,47.53 60.91,47.53 60.9,47.53 56.33,47.53 56.12,47.32 56.1,47.32 56.07,47.28 v1(55.49,47.28)
SG1: length 17
  TOP w0.305: SG1.1 46.75,39.6 U1.5
  TOP w0.381: R2.2 54.4,47.26 SG1.1
SG1R: length 51
  TOP w0.381: v1(52.05,47.22) 52.47,47.65 R2.1 52.47,50.4 C2.1
  INNER_2 w0.381: J16.7 78.7,22.11 73.81,22.11 70.13,25.79 70.13,39.09 61.19,48.03 61.12,48.03 61.11,48.04 56.12,48.04 56.12,48.03 52.86,48.03 v1(52.05,47.22)
SG2: length 15.9
  TOP w0.305: SG2.1 46.25,42.49 U1.6
  TOP w0.381: SG2.1 50.98,47.22 R3.2
SG2R: length 52.4
  TOP w0.381: v1(48.59,47.37) 49.04,47.83 R3.1 49.04,50.42 C3.1
  INNER_2 w0.381: v1(48.59,47.37) 49.76,48.54 55.9,48.54 55.91,48.55 61.32,48.55 61.33,48.54 61.4,48.54 70.64,39.3 70.64,28.09 74.16,24.57 78.78,24.57 J16.10
SG3: length 14.6
  TOP w0.305: SG3.1 46.55,44.72 45.75,43.92 U1.7
  TOP w0.381: SG3.1 47.55,47.2 R4.2
SG3R: length 54.7
  TOP w0.381: v1(44.94,47.35) 45.62,48.04 R4.1 45.62,50.38 C4.1
  INNER_2 w0.381: v1(44.94,47.35) 46.63,49.05 55.69,49.05 55.7,49.06 61.53,49.06 61.54,49.05 61.61,49.05 71.15,39.51 71.15,39.09 71.15,29.81 73.73,27.22 78.67,27.22 J16.13
SG4: length 15.2
  TOP w0.305: U1.8 45.25,42.5 43.06,44.69 SG4.1
  TOP w0.381: SG4.1 44.1,47.26 R5.2
SG4R: length 56.6
  TOP w0.381: v1(41.49,47.24) 42.17,47.92 R5.1 42.17,50.45 C5.1
  INNER_2 w0.381: J16.16 78.65,29.78 74.22,29.78 71.7,32.3 71.7,39.68 61.82,49.56 61.75,49.56 61.75,49.56 55.49,49.56 55.48,49.56 43.46,49.56 43.45,49.55 43.22,49.55 42.18,48.51 42.18,47.93 v1(41.49,47.24)
SG5: length 16.4
  TOP w0.305: SG5.1 44.75,41.1 U1.9
  TOP w0.381: SG5.1 40.66,47.24 R6.2
SG5R: length 37.1
  TOP w0.381: v1(38.33,47.3) 38.33,47.58 38.73,47.98 R6.1 38.73,48.83 38.89,48.99 C6.1
  BOTTOM w0.381: v1(38.33,47.3) 37.93,47.71 37.93,49.31 36.66,50.58 19.72,50.58 16.63,47.5 11.41,47.5 11.03,47.88 J15.2
SG5RX: length 84.9
  INNER_1 w0.381: J16.19 81.3,32.34 81.3,44.63 78.48,47.44 68.91,47.44 65.25,51.1 19.34,51.1 18.61,50.37 J15.3
SG6: length 17.6
  TOP w0.305: SG6.1 44.25,38.25 U1.10
  TOP w0.381: SG6.1 37.29,47.18 R7.2
SG6R: length 60
  TOP w0.381: v1(34.96,47.32) 34.96,47.88 35.36,48.28 R7.1 35.36,50.43 C7.1
  INNER_2 w0.381: J16.22 78.82,34.69 74.09,34.69 72.75,36.03 72.75,40.06 62.24,50.57 62.17,50.57 62.17,50.58 55.07,50.58 55.06,50.57 43.04,50.57 43.03,50.56 36.92,50.56 34.96,48.6 v1(34.96,47.32)
SG7: length 19.6
  TOP w0.305: SG7.1 36.61,42.63 38.08,42.63 43.75,36.97 U1.11
  TOP w0.381: SG7.1 33.92,47.21 R8.2
SG7R: length 61.4
  TOP w0.381: C8.1 32.27,49.71 31.99,49.43 R8.1 31.99,47.77 v1(31.6,47.38)
  INNER_2 w0.381: v1(31.6,47.38) 32,47.79 32,48.69 34.39,51.07 42.82,51.07 42.83,51.08 54.85,51.08 54.86,51.09 62.38,51.09 62.38,51.08 62.45,51.08 73.29,40.24 73.29,38.03 73.91,37.41 78.64,37.41 J16.25
SG8: length 21.8
  TOP w0.305: U1.12 43.24,35.9 37.71,41.44 34.41,41.44 SG8.1
  TOP w0.381: R9.2 30.62,47.25 SG8.1
SG8R: length 64.2
  TOP w0.381: C9.1 28.69,50.42 R9.1 28.69,47.67 v1(27.98,46.95)
  INNER_2 w0.381: J16.28 78.64,39.95 74.3,39.95 62.66,51.59 62.59,51.59 62.59,51.6 54.65,51.6 54.64,51.59 42.62,51.59 42.61,51.58 31.07,51.58 28.69,49.2 28.69,47.66 v1(27.98,46.95)
SG9: length 19.9
  TOP w0.305: U1.13 40.75,33.19 32.05,41.89 SG9.1
  TOP w0.381: SG9.1 27.27,42.97 R10.2
SG9R: length 71
  TOP w0.381: v1(27.17,40.43) 26.85,40.43 26.24,41.04 R10.1 25.47,41.04 25.19,41.32 C10.1
  INNER_2 w0.381: v1(27.17,40.43) 27.17,41.18 27.02,41.34 27.02,48.78 30.34,52.1 30.85,52.1 30.86,52.09 42.4,52.09 42.41,52.1 54.43,52.1 54.44,52.1 62.8,52.1 62.8,52.1 62.87,52.1 63.3,51.67 63.31,51.67 72.49,42.49 78.64,42.49 J16.31
SG10: length 18.7
  TOP w0.305: U1.14 40.22,32.69 34.54,38.37 SG10.1
  TOP w0.381: R11.2 27.2,39.52 SG10.1
SG10R: length 75.2
  TOP w0.381: v1(27.23,36.86) 26.96,36.86 26.22,37.59 R11.1 24.04,37.59 C11.1
  INNER_2 w0.381: v1(27.23,36.86) 26.4,37.68 26.4,49.04 29.97,52.61 54.22,52.61 54.23,52.61 63.21,52.61 70.88,44.94 78.73,44.94 J16.34
SG11: length 17.4
  TOP w0.305: U1.15 39.79,32.19 37.13,34.85 SG11.1
  TOP w0.381: SG11.1 27.31,35.89 R12.2
SG11R: length 74.8
  TOP w0.381: R12.1 25.46,33.96 25.18,34.24 C12.1 23.8,33.42 v1(24,33.22)
  INNER_1 w0.381: J16.32 76.28,42.31 74.41,42.31 74.4,42.3 71.08,42.3 63.48,49.9 27.92,49.9 24,45.98 v1(24,33.22)
SG12: length 17.3
  TOP w0.305: SG12.1 30.21,31.17 32.7,28.69 U1.22
  TOP w0.381: SG12.1 27.35,32.17 R13.2
SG12R: length 78.9
  TOP w0.381: R13.1 25.49,30.24 25.21,30.52 C13.1 24.32,29.96 v1(24.32,29.45)
  INNER_1 w0.381: v1(24.32,29.45) 24.88,30.01 24.88,46.14 28.13,49.39 62.42,49.39 72.03,39.78 76.27,39.78 J16.29
SG13: length 17.4
  TOP w0.305: SG13.1 29.44,26.44 32.75,26.44 34.49,28.19 U1.23
  TOP w0.381: SG13.1 27.47,28.42 R14.2
SG13R: length 82.6
  TOP w0.381: R14.1 24.77,26.49 24.61,26.65 C14.1 23.79,26.58 23.79,26.21 24.17,25.83 v1(24.67,25.83)
  INNER_1 w0.381: J16.26 76.03,37.48 72.67,37.48 61.39,48.76 28.26,48.76 25.52,46.02 25.52,26.67 v1(24.67,25.83)
SG14: length 18
  TOP w0.305: R15.2 27.35,24.67 SG14.1 31.13,23.62 35.19,27.68 U1.24
SG14R: length 86.5
  TOP w0.381: v1(26.77,21.68) 26.77,22.23 26.26,22.74 R15.1 24.7,22.74 24.61,22.82 C15.1
  INNER_1 w0.381: J16.23 76.06,34.91 73.74,34.91 60.48,48.17 28.39,48.17 26.27,46.05 26.27,22.75 26.77,22.26 v1(26.77,21.68)
SG15: length 21.5
  TOP w0.305: U1.25 43.24,24.48 39.92,21.15 33.67,21.15 32.2,19.68 SG15.1 27.22,20.78 R16.2
SG15R: length 74.6
  TOP w0.381: C16.1 25.04,19.26 25.45,18.85 R16.1 26.22,18.85 v1(27.09,17.97)
  INNER_1 w0.381: v1(27.09,17.97) 27.09,13.15 29.08,11.17 61.78,11.17 65.36,14.75 70.05,14.75 70.43,15.13 70.43,26.31 73.86,29.74 76.15,29.74 J16.20
SG16: length 23.5
  TOP w0.305: U1.26 43.75,24.11 39.93,20.29 36.09,20.29 SG16.1 28.38,12.59 R17.2
SG16R: length 63.8
  TOP w0.381: R17.1 30.31,10.49 30.11,10.29 C17.1 30.62,9.3 31.05,9.73 v1(31.05,9.97)
  INNER_1 w0.381: v1(31.05,9.97) 31.62,10.54 55.74,10.54 56.42,9.86 61.22,9.86 65.53,14.17 70.63,14.17 71.01,14.55 71.01,24.38 73.93,27.3 76.26,27.3 J16.17
SG17: length 20.8
  TOP w0.305: U1.27 44.25,23.81 39.63,19.19 38.4,19.19 SG17.1 31.78,12.57 R18.2
SG17R: length 58.8
  TOP w0.381: R18.1 33.46,11.09 C18.1 33.46,9.17 v1(34.22,8.42)
  INNER_1 w0.381: v1(34.22,8.42) 36.25,8.42 37.18,9.35 61.43,9.35 65.67,13.6 71.09,13.6 71.58,14.09 71.58,22.65 73.46,24.53 76.03,24.53 J16.14
SG18: length 18.9
  TOP w0.305: U1.28 44.75,23.48 36.24,14.98 SG18.1 35.22,12.55 R19.2
SG18R: length 54.2
  TOP w0.381: v1(37.57,8.15) 37.27,8.15 36.89,8.53 C19.1 36.89,11.05 R19.1
  INNER_1 w0.381: v1(37.57,8.15) 40.13,8.15 40.82,8.84 61.64,8.84 65.88,13.09 71.3,13.09 71.31,13.1 71.39,13.1 72.24,13.94 72.24,21.34 73.04,22.15 76.19,22.15 J16.11
SG19: length 17.6
  TOP w0.305: U1.29 45.25,23.18 39.75,17.68 SG19.1 38.74,12.55 R20.2
SG19R: length 47.9
  TOP w0.381: v1(41.25,8.27) 41.25,8.35 40.43,9.17 C20.1 40.43,11.09 R20.1
  INNER_1 w0.381: J16.8 76.15,19.57 73.54,19.57 72.89,18.92 72.89,13.82 71.61,12.54 66.05,12.54 61.79,8.27 v1(41.25,8.27)
SG20: length 16.3
  TOP w0.305: U1.30 45.75,22.86 43.13,20.25 SG20.1 42.27,12.63 R21.2
SG20R: length 43.1
  TOP w0.381: v1(44.53,7.7) 43.92,8.32 C21.1 43.92,10.6 44.2,10.88 R21.1
  INNER_1 w0.381: J16.5 76.15,17.03 73.99,17.03 73.41,16.46 73.41,13.38 71.97,11.94 66.38,11.94 62.13,7.7 v1(44.53,7.7)
SP0: length 16.4
  TOP w0.305: U1.47 54.15,32.69 55.61,34.15 61.38,34.15 SP0.1
  TOP w0.381: SP0.1 63.63,33.9 R24.1
SP0R: length 23
  TOP w0.381: R24.2 66.19,31.97 66.31,32.09 C38.1 68.34,32.09 69.49,30.94 69.49,20.73 73.15,17.07 73.15,16.36 73.74,15.77 J16.3
SP1: length 16.7
  TOP w0.305: SP1.1 61.37,36.42 61.34,36.45 56.69,36.45 53.43,33.19 U1.48
  TOP w0.381: SP1.1 63.71,37.46 R25.1
SP1R: length 24.2
  TOP w0.381: J16.6 73.48,18.31 70.07,21.72 70.07,33.93 68.34,35.65 C37.1 66.33,35.65 66.2,35.53 R25.2
SP2: length 19.9
  TOP w0.305: SP2.1 52.58,39.94 48.75,36.1 U1.1
  TOP w0.381: SP2.1 63.83,41.06 R26.1
SP2R: length 24.6
  TOP w0.381: J16.9 73.74,20.85 70.69,23.89 70.69,36.1 67.58,39.22 C36.1 66.29,39.22 66.2,39.13 R26.2
SP3: length 22.2
  TOP w0.305: U1.2 48.25,36.71 53.1,41.56 60.77,41.56 SP3.1
  TOP w0.381: R27.1 63.75,44.54 SP3.1
SP3R: length 27.1
  TOP w0.381: J16.12 73.57,23.39 71.26,25.69 71.26,41.41 69.81,42.85 C35.1 66.44,42.85 66.2,42.61 R27.2
SP4: length 21.7
  TOP w0.305: SP4.1 56.91,42.76 53.05,42.76 47.75,37.46 U1.3
  TOP w0.381: SP4.1 61.3,47.14 R28.1
SP4R: length 38.5
  TOP w0.381: J16.15 73.47,25.93 72.05,27.35 72.05,43.86 64.29,51.62 60.28,51.62 59.51,50.85 C34.1 59.51,49.7 59.36,49.55 R28.2
SP5: length 15.6
  TOP w0.305: U1.31 46.25,21.66 46.83,21.08 SP5.1 45.77,12.43 R29.1
SP5R: length 45.7
  TOP w0.381: R29.2 47.46,11.09 C33.1 47.96,9.3 48.34,9.68 v1(48.34,9.96)
  BOTTOM w0.381: v1(48.34,9.96) 49.59,8.71 61.53,8.71 65.63,12.81 68.47,12.81 68.47,12.81 69.31,12.81 69.73,12.81 72.07,15.15 72.07,27.06 73.48,28.47 J16.18
SP6: length 16.8
  TOP w0.305: U1.32 46.75,22.91 50.34,19.32 SP6.1 49.27,12.41 R30.1
SP6R: length 44.5
  TOP w0.381: v1(51.8,9.96) 51.8,9.68 51.42,9.3 C32.1 50.94,11.05 R30.2
  BOTTOM w0.381: v1(51.8,9.96) 52.54,9.22 61.27,9.22 65.37,13.32 68.68,13.32 68.68,13.32 69.52,13.32 71.56,15.36 71.56,30.09 72.48,31.01 J16.21
SP7: length 18
  TOP w0.305: U1.33 47.25,23.12 53.67,16.7 SP7.1 52.76,12.53 R31.1
SP7R: length 42.6
  TOP w0.381: v1(55.51,9.96) 54.87,9.32 C31.1 54.41,10.58 54.69,10.86 R31.2
  BOTTOM w0.381: v1(55.51,9.96) 56.08,9.96 56.31,9.73 61.06,9.73 65.16,13.83 68.89,13.83 68.89,13.83 69.31,13.83 70.99,15.5 70.99,32.2 72.33,33.55 J16.24
SP8: length 19.2
  TOP w0.305: R32.1 56.32,12.59 SP8.1 55.46,15.22 55.46,15.8 47.75,23.51 U1.34
SP8R: length 40.8
  TOP w0.381: C30.1 58.07,11.15 R32.2 v1(59.12,10.46)
  BOTTOM w0.381: v1(59.12,10.46) 61.07,10.46 64.95,14.34 69.1,14.34 70.48,15.71 70.48,34.58 71.99,36.09 J16.27
SP9: length 21.7
  TOP w0.305: U1.35 48.25,23.96 56.56,15.65 58.67,15.65 SP9.1 59.87,12.61 R33.1
SP9R: length 42.2
  TOP w0.381: R33.2 61.8,9.5 C29.1 62.33,9.28 63.01,9.96 63.01,13.95 v1(63.91,14.84)
  BOTTOM w0.381: v1(63.91,14.84) 68.89,14.84 69.97,15.92 69.97,36.89 71.7,38.63 J16.30
SP10: length 21.8
  TOP w0.305: R34.1 63.67,17.58 SP10.1 56.6,16.58 48.75,24.43 U1.36
SP10R: length 34.1
  TOP w0.381: v1(68.71,15.51) 68.06,15.51 C28.1 66.68,16.01 66.32,15.65 R34.2
  BOTTOM w0.381: v1(68.71,15.51) 69.46,16.26 69.46,39.08 71.55,41.17 J16.33
SP11: length 18.4
  TOP w0.305: SP11.1 58.99,20.41 51.71,27.68 U1.37
  TOP w0.381: SP11.1 63.71,21.37 R35.1
SP11R: length 32.8
  TOP w0.381: R35.2 66.48,19.44 66.68,19.65 C27.1 67.7,19.65 68.29,19.05 v1(68.89,19.05)
  BOTTOM w0.381: J16.36 72.07,43.71 68.89,40.53 v1(68.89,19.05)
WAKE_B: length 62.1
  TOP w0.305: U1.20 40.57,29.69 40.2,29.31 v1(34.88,29.31)
  TOP w0.381: v1(11.95,11.36) 11.54,11.76 11.54,14.7 12.11,15.27 R64.1 ; R36.1 21.03,28.4 22.17,27.27 v1(22.17,26.07)
  BOTTOM w0.381: WAKE_B.1 14.39,6.42 11.95,8.86 v1(11.95,11.36) 11.95,18.91 15.31,22.27 20.67,22.27 22.17,23.77 v1(22.17,26.07) 23.1,25.14 29.91,25.14 34.08,29.31 v1(34.88,29.31)
N46347: length 11.3
  TOP w0.305: U1.39 55.02,28.69 56.79,26.92 R22.2
N63980: length 17.8
  TOP w0.381: J7.1 18.48,18.91 D2.A
  BOTTOM w0.381: J7.1 17.2,14.82 18.94,13.08 J6.2
N64526: length 9.2
  TOP w0.381: J7.2 20.58,18.47 D2.C 20.58,24.41 20.58,24.41 R36.2
N74267: length 4.9
  TOP w0.381: J3.2 66.53,24.26 66.52,24.26 D3.C 63.72,24.26 63.67,24.31 R23.2
N81888: length 2.9
  TOP w0.381: D5.A 10.89,34.01 11,33.9 J4.2
N159644: length 2.1
  TOP w0.381: J8.5 38.04,4.15 38.05,4.14 R45.2
N159652: length 2.3
  TOP w0.381: J8.8 45.66,3.99 45.67,3.99 R46.2
N165115: length 2.3
  TOP w0.381: R47.2 50.74,4.34 50.82,4.41 J9.1
N222829: length 5.5
  TOP w0.381: U2.8 13.6,7.95 13.6,7.95 C39.1 R43.2
N224295: length 9.5
  TOP w0.381: R62.1 R61.1 24.61,8.81 23.58,9.84 23.58,10.73 22.55,11.76 U2.4
N235544: length 4.8
  TOP w0.381: U2.5 15.92,12.93 15.64,13.2 R63.2 14.44,14.34 14.46,14.36 R64.2
N794881: length 2.4
  TOP w0.381: R44.2 D5.C
N1652480: length 3.1
  TOP w0.381: J17.1 19.52,45.88 R48.1
N1652481: length 3.2
  TOP w0.381: R50.2 24.12,45.76 J17.2
N1652482: length 3.3
  TOP w0.381: J17.3 19.15,50.73 R49.1
N1652483: length 3.3
  TOP w0.381: R51.2 24.34,50.7 J17.4

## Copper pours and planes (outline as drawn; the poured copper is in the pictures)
0 on TOP: 0.74,45.94 4.46,54.92 13.44,58.64 70.94,58.64 79.92,54.92 83.64,45.94 83.64,13.36 79.92,4.38 70.94,0.66 13.44,0.66 4.46,4.38 0.74,13.36 ; 3 cut-outs
0 on BOTTOM: 0.74,45.96 4.46,54.94 13.44,58.66 70.94,58.66 79.92,54.94 83.64,45.96 83.64,13.38 79.92,4.4 70.94,0.68 13.44,0.68 4.46,4.4 0.74,13.38 ; 6 cut-outs

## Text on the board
BOTTOM: 170-28829 REV A | 4 OF 10 | SECONDARY SIDE
Board Geometry/Soldermask Bottom: 8 OF 10 | SECONDARY SOLDERMASK
Ref Des/Silkscreen Bottom: 170-28829 REV A | 10 of 10 | SECONDARY SILKSCREEN
User.Comments: 1 OF 1 | TEST PROBE | 1/1 | 1
TOP: 1 OF 10 | PRIMARY SIDE
Board Geometry/Soldermask Top: 5 OF 10 | PRIMARY SOLDERMASK
Ref Des/Silkscreen Top: VDDQ | VBATP | WAKE | 5.0V | 3.3V | BATT | GND | SPI CONF | 7 OF 10 | FRDM-CD1030EVM | PRIMARY SILKSCREEN
INNER_1: 2 of 10 | INNER LAYER 1
INNER_2: 3 of 10 | INNER LAYER 2
DIMENSION: GRID ORIGIN | PRIMARY DATUM
BODY_CENTER: 23. COPPER SHAVING IS ALLOWED IN FRONT OF PADS OF CONNECTORS J5 AND J7 | 22. | NO INTENTIONAL SHORTS ON DESIGN. | IN ORDER TO KEEP A 0.010" CLEARANCE FROM THE EDGE OF THE BOARDS. | 16 | 17 | 8
PASTEMASK_TOP: 6 OF 10 | PASTEMASK TOP
User.5: 9 OF 10 | SECONDARY PASTEMASK
User.19: FIGURE | SIZE | 10.0 | 40.0 | 41.0 | 51.0 | DRILL CHART: TOP to BOTTOM | ALL UNITS ARE IN MILS | TOLERANCE | +0.0/-10.0 | +3.0/-3.0 | PLATED | QTY | 89 | 130 | 6 | 2
